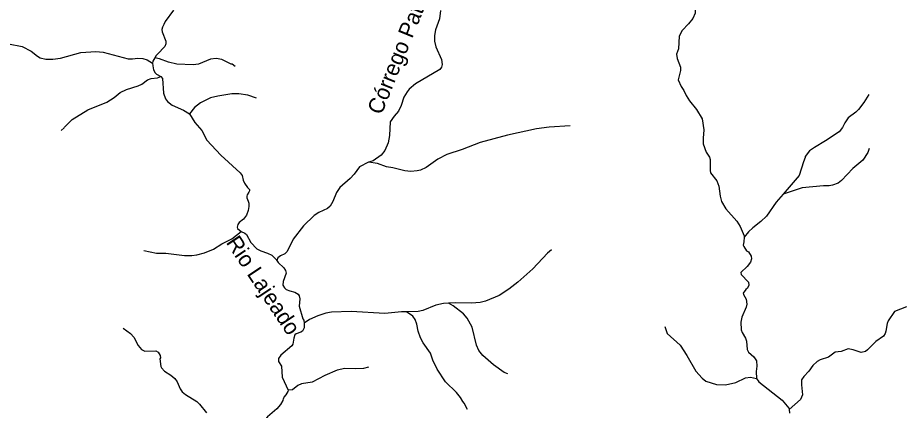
# Model space of a CAD drawing. Extents: x 280.4 to 335.6, y 8893.9 to 8949.5.
# Drawn here: x 309.86 to 321.05, y 8909.74 to 8914.7 of the extents above; entities that cross this region are included whole.
import ezdxf
from ezdxf.enums import TextEntityAlignment as Align

# ---------------------------------------------------------------- set-up
doc = ezdxf.new("R2010")
doc.units = 0
doc.header["$LTSCALE"] = 0.064
doc.layers.add('61', color=7, linetype='Continuous')
doc.layers.add('7', color=7, linetype='Continuous', lineweight=25)

msp = doc.modelspace()

# ---------------------------------------------------------------- linework, layer by layer
at = {"layer": '7'}
for points in [[(311.8321, 8914.792), (311.7255, 8914.6495), (311.7073, 8914.6085), (311.6916, 8914.5758), (311.6833, 8914.5474), (311.6856, 8914.519), (311.7317, 8914.399), (311.7346, 8914.3672), (311.7206, 8914.3341), (311.6279, 8914.2374), (311.6101, 8914.2165), (311.5943, 8914.1904)], [(315.2025, 8914.7882), (315.1907, 8914.6809), (315.1419, 8914.5429), (315.1271, 8914.4709), (315.1287, 8914.4005), (315.1451, 8914.3285), (315.2179, 8914.1677), (315.2262, 8914.1039), (315.2166, 8914.0715), (315.1933, 8914.043), (314.8897, 8913.8596), (314.8062, 8913.7917), (314.7812, 8913.7618), (314.7404, 8913.6911), (314.7083, 8913.5856), (314.6744, 8913.5173), (314.6165, 8913.4516), (314.5673, 8913.3796), (314.5577, 8913.2107), (314.5417, 8913.1147), (314.5021, 8913.0195), (314.4557, 8912.9604), (314.354, 8912.8902), (314.2959, 8912.8744)], [(318.4184, 8914.8339), (318.4207, 8914.7532), (318.3922, 8914.6846), (318.3388, 8914.6186), (318.2563, 8914.5361), (318.2184, 8914.4606), (318.2088, 8914.3021), (318.185, 8914.2343), (318.1947, 8914.1791), (318.236, 8914.0694)], [(309.7455, 8914.3651), (309.9167, 8914.3301), (310.0318, 8914.2726), (310.1129, 8914.2091), (310.147, 8914.1903), (310.2181, 8914.1703), (310.3069, 8914.1703), (310.4021, 8914.1861), (310.6616, 8914.2571), (310.8514, 8914.2693), (310.9418, 8914.2594), (311.2561, 8914.1752), (311.3137, 8914.175), (311.3784, 8914.1846), (311.4416, 8914.1815), (311.4999, 8914.1622), (311.5653, 8914.1235)], [(311.5943, 8914.1904), (311.5807, 8914.1695), (311.5708, 8914.1455), (311.5653, 8914.1235)], [(311.5653, 8914.1235), (311.5683, 8914.089), (311.5771, 8914.037), (311.5971, 8913.9995), (311.6157, 8913.9813), (311.6706, 8913.9522)], [(312.6095, 8914.0792), (312.573, 8914.1087), (312.5591, 8914.1101), (312.4407, 8914.1671), (312.3699, 8914.1798), (312.299, 8914.1708), (312.1446, 8914.109), (312.0789, 8914.0999), (311.8736, 8914.1102), (311.7678, 8914.1327), (311.6526, 8914.1768), (311.5943, 8914.1904)], [(318.236, 8914.0694), (318.2357, 8914.0272), (318.2077, 8913.9131), (318.244, 8913.8281), (318.2776, 8913.7752), (318.3053, 8913.7154), (318.3512, 8913.6458), (318.4375, 8913.5385), (318.511, 8913.4193), (318.5318, 8913.2818), (318.5208, 8913.1755), (318.521, 8913.1053), (318.5579, 8912.999), (318.6005, 8912.9356), (318.61, 8912.9043), (318.6087, 8912.7693), (318.6137, 8912.7377), (318.6955, 8912.6365), (318.7193, 8912.5694), (318.7349, 8912.4438), (318.7519, 8912.3776), (318.809, 8912.2825), (318.948, 8912.1279), (318.9899, 8912.0609), (319.0385, 8911.9434), (319.0381, 8911.9247)], [(310.4121, 8913.2726), (310.45, 8913.3044), (310.4541, 8913.3161), (310.5517, 8913.4122), (310.7494, 8913.5311), (310.9899, 8913.6305), (311.0809, 8913.6888), (311.1556, 8913.7502), (311.2377, 8913.7896), (311.3836, 8913.8354), (311.4296, 8913.8585), (311.5037, 8913.9129), (311.5493, 8913.929), (311.6273, 8913.9383), (311.6706, 8913.9522)], [(311.6706, 8913.9522), (311.6896, 8913.9279), (311.7042, 8913.7417), (311.7299, 8913.6723), (311.7534, 8913.6389), (311.8149, 8913.5906), (311.9567, 8913.5292), (312.0347, 8913.4808)], [(312.8798, 8913.6808), (312.7682, 8913.718), (312.6578, 8913.7352), (312.5682, 8913.7352), (312.3898, 8913.7066), (312.2995, 8913.6824), (312.1717, 8913.6233), (312.0949, 8913.5625), (312.0347, 8913.4808)], [(320.6162, 8913.7266), (320.5508, 8913.6236), (320.4846, 8913.5351), (320.4521, 8913.503), (320.3552, 8913.4329), (320.3129, 8913.3689), (320.2842, 8913.3109), (320.2408, 8913.2565), (320.0687, 8913.1413), (319.9297, 8913.0593), (319.867, 8913.0135), (319.81, 8912.9444), (319.8109, 8912.9318), (319.7892, 8912.8787), (319.7328, 8912.7022), (319.5334, 8912.468)], [(312.0347, 8913.4808), (312.0999, 8913.3746), (312.1864, 8913.274), (312.2501, 8913.1494), (312.4297, 8912.9608), (312.6716, 8912.7394), (312.696, 8912.705), (312.7089, 8912.6453), (312.7277, 8912.6056), (312.7667, 8912.5545), (312.7894, 8912.5265), (312.7915, 8912.5109), (312.7832, 8912.4934), (312.7612, 8912.4615), (312.7586, 8912.4447), (312.7588, 8912.4225), (312.7747, 8912.3818), (312.7824, 8912.3535), (312.7832, 8912.3131), (312.7731, 8912.2615), (312.7517, 8912.2025), (312.7157, 8912.1526), (312.6615, 8912.109), (312.645, 8912.087), (312.6357, 8912.0536), (312.6387, 8912.0361), (312.6836, 8911.9962)], [(316.8412, 8913.3304), (316.5767, 8913.3131), (316.4185, 8913.2921), (316.0483, 8913.2116), (315.706, 8913.1211), (315.4757, 8913.0332), (315.2822, 8912.9701), (315.168, 8912.9112), (315.0208, 8912.8041), (314.9499, 8912.7728), (314.9071, 8912.7615), (314.8279, 8912.7566), (314.7536, 8912.7644), (314.6001, 8912.8011), (314.5233, 8912.8123), (314.4082, 8912.8538), (314.2959, 8912.8744)], [(320.6196, 8913.0429), (320.6006, 8912.9934), (320.5373, 8912.8973), (320.4111, 8912.7916), (320.2703, 8912.6413), (320.2277, 8912.6083), (320.1575, 8912.5829), (320.114, 8912.5747), (320.0439, 8912.5759), (319.7745, 8912.5502), (319.5334, 8912.468)], [(314.2959, 8912.8744), (314.1797, 8912.8147), (314.1131, 8912.7214), (314.064, 8912.6643), (313.9307, 8912.551), (313.8905, 8912.4904), (313.8418, 8912.3774), (313.8091, 8912.3184), (313.7756, 8912.2864), (313.6654, 8912.2367), (313.6078, 8912.2015), (313.4719, 8912.0704), (313.3412, 8911.9016), (313.265, 8911.7452), (313.2358, 8911.7136), (313.1824, 8911.6913), (313.1483, 8911.6648), (313.1379, 8911.6298)], [(319.5334, 8912.468), (319.4462, 8912.3656), (319.3207, 8912.189), (319.2517, 8912.1221), (319.1485, 8912.0428), (319.0949, 8911.992), (319.0381, 8911.9247)], [(311.4543, 8911.7593), (311.616, 8911.7254), (311.7341, 8911.7232), (311.9694, 8911.6947), (312.0629, 8911.6947), (312.1261, 8911.7041), (312.2221, 8911.7295), (312.3347, 8911.7746), (312.4404, 8911.8401), (312.5675, 8911.9043), (312.6836, 8911.9962)], [(312.6836, 8911.9962), (312.7319, 8911.9771), (312.7519, 8911.9617), (312.8082, 8911.8578), (312.8841, 8911.7774), (312.9343, 8911.7515), (313.0199, 8911.7224), (313.071, 8911.6973)], [(319.0381, 8911.9247), (319.037, 8911.8689), (319.0278, 8911.8271), (319.0341, 8911.8065), (319.0684, 8911.7518), (319.0935, 8911.7389), (319.1298, 8911.6881), (319.1313, 8911.6546), (319.1205, 8911.6107), (319.0783, 8911.5565), (318.9991, 8911.4795), (319.0005, 8911.4555), (319.0961, 8911.3602), (319.0995, 8911.3204), (319.0836, 8911.2843), (319.0593, 8911.2654), (319.028, 8911.2212), (319.0301, 8911.2005), (319.0659, 8911.1443), (319.0738, 8911.0806), (319.0654, 8911.0438), (319.0112, 8910.9157), (318.9974, 8910.8541), (319.0033, 8910.7559), (319.0146, 8910.7238), (319.0576, 8910.6494), (319.0709, 8910.6128), (319.0793, 8910.5073), (319.0962, 8910.4736), (319.1609, 8910.4162), (319.1955, 8910.3655), (319.2018, 8910.2998), (319.1924, 8910.2288), (319.1957, 8910.1423)], [(316.606, 8911.7641), (316.5565, 8911.7241), (316.371, 8911.528), (316.1804, 8911.3568), (316.0674, 8911.2709), (315.9437, 8911.1891), (315.7707, 8911.1165), (315.7046, 8911.1011), (315.5955, 8911.0917), (315.3979, 8911.0981), (315.3053, 8911.0926)], [(313.071, 8911.6973), (313.1291, 8911.6429), (313.1379, 8911.6298)], [(313.1379, 8911.6298), (313.1531, 8911.607), (313.2259, 8911.5404), (313.2474, 8911.5062), (313.2525, 8911.4715), (313.2151, 8911.3681), (313.2114, 8911.3187), (313.2311, 8911.2863), (313.2536, 8911.2676), (313.3, 8911.2487), (313.3647, 8911.2339), (313.4052, 8911.2075), (313.4185, 8911.1852), (313.4255, 8911.1492), (313.4175, 8911.0549), (313.4642, 8910.8945), (313.4783, 8910.8772), (313.48, 8910.8407)], [(315.3053, 8911.0926), (315.243, 8911.0889), (315.1462, 8911.0661), (314.9818, 8911.0005), (314.9216, 8910.9861), (314.7723, 8910.985)], [(316.0556, 8910.201), (316.0059, 8910.2172), (315.8729, 8910.314), (315.7405, 8910.4317), (315.6885, 8910.4954), (315.6592, 8910.5644), (315.6017, 8910.79), (315.5409, 8910.9051), (315.4961, 8910.9594), (315.3656, 8911.0585), (315.3053, 8911.0926)], [(314.7723, 8910.985), (314.71, 8910.9845), (314.4986, 8910.9606), (314.0764, 8910.9861), (313.8267, 8910.9794), (313.7565, 8910.9665), (313.6532, 8910.9352), (313.5498, 8910.8869), (313.48, 8910.8407)], [(315.5434, 8909.7521), (315.503, 8909.8323), (315.4852, 8909.8501), (315.4577, 8909.9008), (315.4069, 8909.9642), (315.2659, 8910.102), (315.1632, 8910.26), (315.1085, 8910.3753), (315.0771, 8910.4638), (314.9851, 8910.5946), (314.9493, 8910.6557), (314.9197, 8910.7399), (314.9047, 8910.8278), (314.8851, 8910.8859), (314.8556, 8910.9293), (314.7723, 8910.985)], [(321.0889, 8911.0487), (320.9394, 8910.9881), (320.8589, 8910.8693), (320.846, 8910.8367), (320.8314, 8910.7407), (320.8203, 8910.7095), (320.7984, 8910.6783), (320.7029, 8910.6114), (320.5992, 8910.5026), (320.5727, 8910.482), (320.518, 8910.4715), (320.4158, 8910.5062), (320.3556, 8910.5155), (320.2669, 8910.4847), (320.1914, 8910.475), (320.1053, 8910.4097), (320.0013, 8910.3795), (319.9626, 8910.3555), (319.9057, 8910.3048), (319.8576, 8910.2329), (319.7938, 8910.1673), (319.7652, 8910.127), (319.7649, 8910.0609), (319.7777, 8909.9384), (319.7525, 8909.8758), (319.6066, 8909.7499)], [(311.1962, 8910.7778), (311.2859, 8910.7119), (311.3303, 8910.6642), (311.3849, 8910.5603), (311.4265, 8910.5096), (311.4687, 8910.4888), (311.6092, 8910.4919), (311.6387, 8910.4748), (311.6629, 8910.4335), (311.6644, 8910.4031), (311.6583, 8910.3919), (311.6689, 8910.2941), (311.6772, 8910.275), (311.7155, 8910.2359), (311.7986, 8910.1857), (311.8492, 8910.1428), (311.8757, 8910.0985), (311.9131, 8910.0109), (311.9408, 8909.973), (311.9842, 8909.9394), (312.1257, 8909.8533), (312.1598, 8909.8191), (312.2456, 8909.7111)], [(313.48, 8910.8407), (313.4828, 8910.7812), (313.4594, 8910.7406), (313.4409, 8910.7278), (313.3784, 8910.7051), (313.3653, 8910.6924), (313.3504, 8910.6518), (313.3392, 8910.5765), (313.325, 8910.5526), (313.1846, 8910.438), (313.1573, 8910.3956), (313.1571, 8910.3561), (313.1951, 8910.2992), (313.204, 8910.1596), (313.2777, 8909.9961)], [(318.0357, 8910.7979), (318.0674, 8910.7114), (318.23, 8910.5633), (318.3164, 8910.4338), (318.4296, 8910.2361), (318.5096, 8910.1465), (318.557, 8910.1093), (318.6909, 8910.0665), (318.8021, 8910.0634), (318.9351, 8910.0933), (319.0587, 8910.1514), (319.122, 8910.1577), (319.1957, 8910.1423)], [(314.2938, 8910.2873), (314.2323, 8910.2674), (314.1302, 8910.2632), (313.9949, 8910.268), (313.8977, 8910.2458), (313.7442, 8910.1812), (313.5811, 8910.0972), (313.447, 8910.0746), (313.4, 8910.0536), (313.3333, 8909.9982), (313.2777, 8909.9961)], [(319.1957, 8910.1423), (319.2265, 8910.0997), (319.5207, 8909.8693), (319.6037, 8909.767), (319.6066, 8909.7499)], [(313.2777, 8909.9961), (313.275, 8909.978), (313.25, 8909.9355), (313.2249, 8909.9078), (313.2207, 8909.8915), (313.2144, 8909.8897), (313.211, 8909.8641), (313.1829, 8909.8126), (313.136, 8909.7596), (313.0193, 8909.6603), (312.969, 8909.6008), (312.9395, 8909.5529), (312.9378, 8909.5154)], [(319.6066, 8909.7499), (319.6145, 8909.7031)]]:
    msp.add_lwpolyline(points, dxfattribs=at)

# ---------------------------------------------------------------- texts
at = {"layer": '61'}
for s, rotation, p in [('Córrego Patrona', 68.098, (314.8262, 8914.3764)), ('Rio Lajeado', 303.69, (312.8835, 8911.2648))]:
    msp.add_text(s, height=0.2, rotation=rotation, dxfattribs=at).set_placement(p, align=Align.CENTER)

doc.saveas('drawing.dxf')
